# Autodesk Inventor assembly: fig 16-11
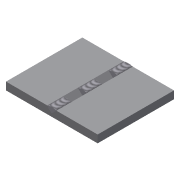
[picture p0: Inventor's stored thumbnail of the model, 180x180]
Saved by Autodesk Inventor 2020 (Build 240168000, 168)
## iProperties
Created: 2005-03
Part Number: fig 16-11
Document SubType Name: Weldment
Designer: CADCIM
Manufacturer: Standard
Standards Organization: Custom
Author: CADCIM
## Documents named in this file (2)
- D:\Autodesk Inventor_2020\Resources\Resources\Inventor_2020_Part\Inventor_2020_Part\c16_Inv_2020_prt\fig 16-11\fig 16-11.iam
- D:\Autodesk Inventor_2020\Resources\Resources\Inventor_2020_Part\Inventor_2020_Part\c16_Inv_2020_prt\fig 16-11\Part1.ipt
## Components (2 placed, 1 different names)
1. Part1:1 — Mate:1, Flush:1, Flush:2
2. Part1:2 — Mate:1, Flush:1, Flush:2
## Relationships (3: Flush 2, Mate 1)
- Mate:1: Part1:1 ↔ Part1:2
- Flush:1: Part1:1 ↔ Part1:2
- Flush:2: Part1:1 ↔ Part1:2
